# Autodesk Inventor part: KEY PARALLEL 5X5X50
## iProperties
Created: 2007-06
Part Number: KEY PARALLEL 5X5X50
Document SubType Name: Modeling
Designer: Andy Moles
Material: Steel
Density: 7.85 g/cm^3
Author: Andy Moles
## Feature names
1. Extrusion4
2. Fillet1
